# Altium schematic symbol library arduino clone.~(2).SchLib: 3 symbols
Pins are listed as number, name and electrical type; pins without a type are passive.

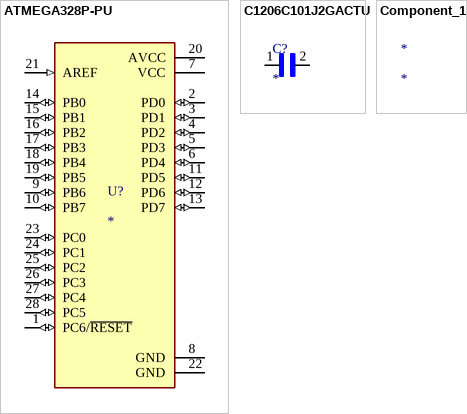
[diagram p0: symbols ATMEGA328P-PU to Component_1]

## ATMEGA328P-PU
designator U?
ATmega Series 20 MHz 32 KB Flash 2 KB SRAM 8-Bit Microcontroller - DIP-28; MP: ATMEGA328P-PU
footprint DIP794W46P254L2967H457Q28B
pins: 1 PC6/~{RESET} (io), 2 PD0 (io), 3 PD1 (io), 4 PD2 (io), 5 PD3 (io), 6 PD4 (io), 7 VCC (power), 8 GND (power), 9 PB6 (io), 10 PB7 (io), 11 PD5 (io), 12 PD6 (io), 13 PD7 (io), 14 PB0 (io), 15 PB1 (io), 16 PB2 (io), 17 PB3 (io), 18 PB4 (io), 19 PB5 (io), 20 AVCC (power), 21 AREF (in), 22 GND (power), 23 PC0 (io), 24 PC1 (io), 25 PC2 (io), 26 PC3 (io), 27 PC4 (io), 28 PC5 (io)

## C1206C101J2GACTU
designator C?
CAP CER 100PF 200V C0G/NP0 1206; MP: C1206C101J2GACTU
footprint CAPC3216X88N
pins: 1, 2

## Component_1
designator *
